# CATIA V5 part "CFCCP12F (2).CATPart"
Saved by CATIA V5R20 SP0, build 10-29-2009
Part number: CFCCP12F (2)
Revision: TUTTO
Definition: NON CONOSCIUTO
Nomenclature: CFCCP12F (2)
Source: Unknown
Bounding box of the stored display mesh (mm): x -60 to 60, y -39 to 39, z -65 to 0
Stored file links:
  C:\Users\Utente\Desktop\IO LAVORO\3D X SITO CF\X 3D SITO CF 27-09-2020\CFCCP\CFCCP12F\CFCCP12F (2).CATPart
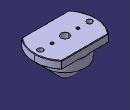
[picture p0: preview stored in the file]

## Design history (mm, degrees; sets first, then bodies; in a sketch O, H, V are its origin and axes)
Body1 "Foro filettato M5-1" (main body)
  Solid1: solid without history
